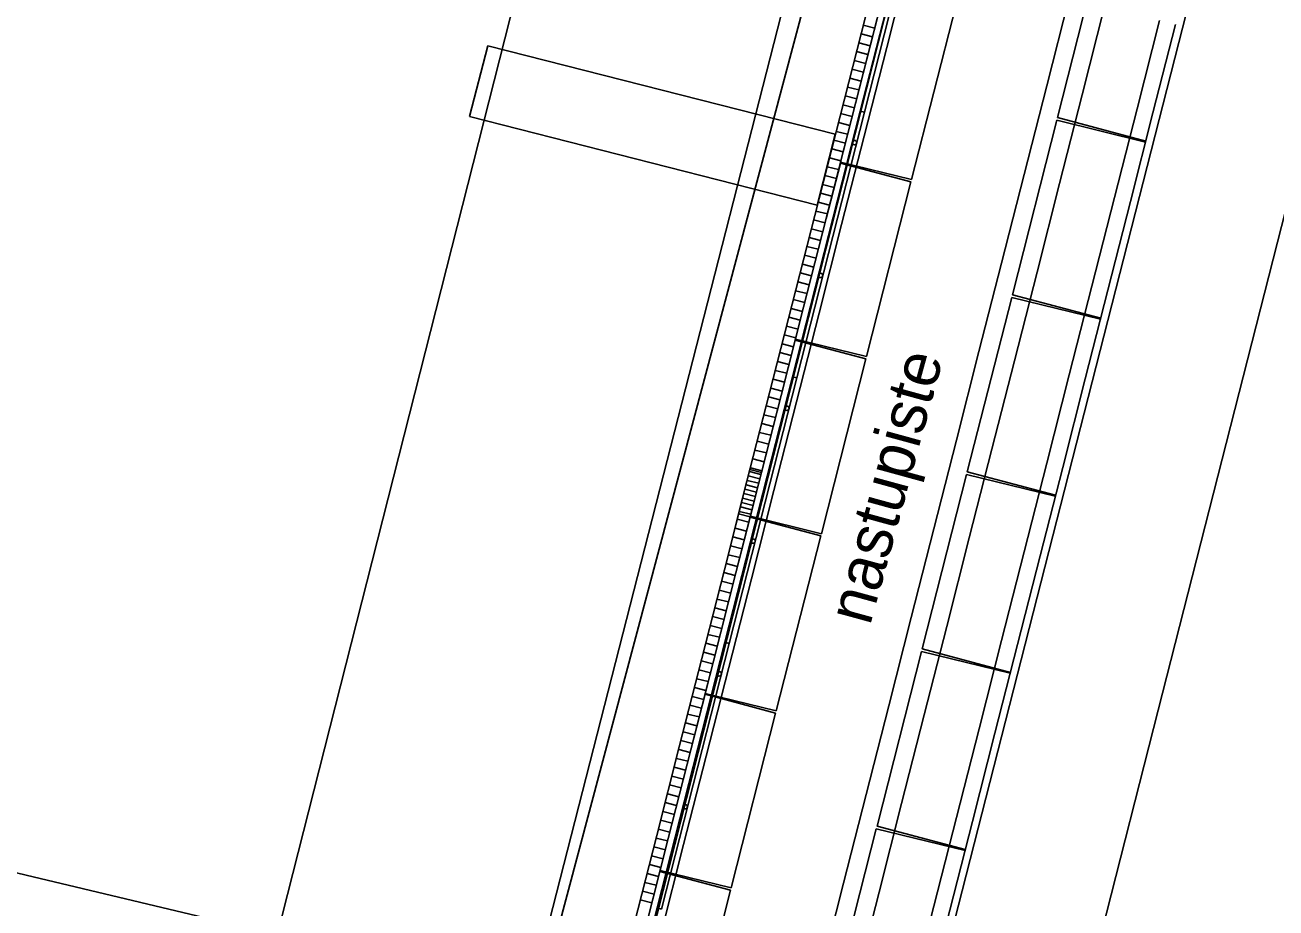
# Model space of a CAD drawing. Extents: x -733601 to -733291, y -1137892 to -1137187.
# Drawn here: x -733465.26 to -733451.57, y -1137672.4 to -1137662.74 of the extents above; entities that cross this region are included whole.
import ezdxf

# ---------------------------------------------------------------- set-up
doc = ezdxf.new("R2010")
doc.units = 0
for name, color, linetype in [('Rozvrzeni', 7, 'Continuous'), ('SIT_PUV_BUS', 7, 'Continuous'), ('SIT_PUV_ZELEZNICE', 7, 'Continuous')]:
    doc.layers.add(name, color=color, linetype=linetype)

msp = doc.modelspace()

# ---------------------------------------------------------------- linework, layer by layer
at = {"layer": 'Rozvrzeni'}
msp.add_lwpolyline([(-733564.934, -1137648.317), (-733492.008, -1137341.875), (-733347.542, -1137376.254), (-733420.468, -1137682.696)], close=True, dxfattribs=at)
at = {"layer": 'SIT_PUV_BUS'}
for p, q in [((-733456.56, -1137649.32), (-733464.08, -1137678.93)), ((-733453.45, -1137650.19), (-733460.1, -1137675.18)), ((-733455.27, -1137660.37), (-733460.18, -1137679.73)), ((-733452.43, -1137662.15), (-733466.53, -1137717.32))]:
    msp.add_line(p, q, dxfattribs=at)
at = {"layer": 'SIT_PUV_ZELEZNICE'}
for p, q in [((-733453.472, -1137661.842), (-733453.958, -1137663.751)), ((-733456.116, -1137663.679), (-733455.768, -1137662.313)), ((-733456.07, -1137663.691), (-733455.721, -1137662.325)), ((-733455.067, -1137662.515), (-733455.555, -1137664.428)), ((-733455.958, -1137662.77), (-733456.084, -1137662.738)), ((-733455.983, -1137662.867), (-733456.108, -1137662.835)), ((-733460.193, -1137662.964), (-733460.392, -1137663.739)), ((-733456.39, -1137663.933), (-733460.193, -1137662.964)), ((-733456.007, -1137662.964), (-733456.133, -1137662.931)), ((-733456.057, -1137663.157), (-733456.183, -1137663.125)), ((-733456.032, -1137663.06), (-733456.158, -1137663.028)), ((-733456.081, -1137663.254), (-733456.207, -1137663.222)), ((-733456.131, -1137663.448), (-733456.257, -1137663.416)), ((-733456.106, -1137663.351), (-733456.232, -1137663.319)), ((-733456.155, -1137663.545), (-733456.281, -1137663.513)), ((-733456.857, -1137666.586), (-733456.116, -1137663.679)), ((-733456.81, -1137666.598), (-733456.07, -1137663.691)), ((-733456.18, -1137663.642), (-733456.306, -1137663.61)), ((-733456.07, -1137663.691), (-733456.116, -1137663.679)), ((-733456.116, -1137663.679), (-733456.07, -1137663.691)), ((-733460.392, -1137663.739), (-733456.587, -1137664.709)), ((-733456.229, -1137663.836), (-733456.355, -1137663.804)), ((-733456.205, -1137663.739), (-733456.331, -1137663.707)), ((-733453.966, -1137663.78), (-733454.452, -1137665.689)), ((-733452.994, -1137664.018), (-733453.966, -1137663.78)), ((-733453.958, -1137663.751), (-733452.992, -1137664.008)), ((-733456.587, -1137664.709), (-733456.39, -1137663.933)), ((-733456.254, -1137663.933), (-733456.38, -1137663.901)), ((-733456.303, -1137664.126), (-733456.429, -1137664.094)), ((-733456.279, -1137664.03), (-733456.405, -1137663.997)), ((-733456.328, -1137664.223), (-733456.454, -1137664.191)), ((-733456.334, -1137664.248), (-733455.561, -1137664.453)), ((-733455.555, -1137664.428), (-733456.332, -1137664.238)), ((-733456.377, -1137664.417), (-733456.503, -1137664.385)), ((-733456.353, -1137664.32), (-733456.479, -1137664.288)), ((-733456.402, -1137664.514), (-733456.528, -1137664.482)), ((-733455.561, -1137664.453), (-733456.048, -1137666.366)), ((-733456.427, -1137664.611), (-733456.553, -1137664.579)), ((-733456.476, -1137664.805), (-733456.602, -1137664.773)), ((-733456.452, -1137664.708), (-733456.578, -1137664.676)), ((-733456.501, -1137664.902), (-733456.627, -1137664.87)), ((-733456.55, -1137665.095), (-733456.676, -1137665.063)), ((-733456.526, -1137664.999), (-733456.652, -1137664.967)), ((-733456.575, -1137665.192), (-733456.701, -1137665.16)), ((-733456.6, -1137665.289), (-733456.726, -1137665.257)), ((-733456.649, -1137665.483), (-733456.775, -1137665.451)), ((-733456.624, -1137665.386), (-733456.75, -1137665.354)), ((-733456.674, -1137665.58), (-733456.8, -1137665.548)), ((-733456.723, -1137665.774), (-733456.849, -1137665.742)), ((-733456.698, -1137665.677), (-733456.824, -1137665.645)), ((-733454.459, -1137665.719), (-733454.946, -1137667.628)), ((-733453.488, -1137665.956), (-733454.459, -1137665.719)), ((-733454.452, -1137665.689), (-733453.485, -1137665.946)), ((-733456.748, -1137665.871), (-733456.874, -1137665.839)), ((-733456.772, -1137665.968), (-733456.898, -1137665.936)), ((-733456.822, -1137666.161), (-733456.948, -1137666.129)), ((-733456.797, -1137666.065), (-733456.923, -1137666.032)), ((-733456.847, -1137666.258), (-733456.972, -1137666.226)), ((-733456.828, -1137666.186), (-733456.055, -1137666.391)), ((-733456.048, -1137666.366), (-733456.826, -1137666.176)), ((-733456.896, -1137666.452), (-733457.022, -1137666.42)), ((-733456.871, -1137666.355), (-733456.997, -1137666.323)), ((-733456.055, -1137666.391), (-733456.542, -1137668.304)), ((-733456.921, -1137666.549), (-733457.047, -1137666.517)), ((-733457.597, -1137669.493), (-733456.857, -1137666.586)), ((-733457.551, -1137669.505), (-733456.81, -1137666.598)), ((-733456.97, -1137666.743), (-733457.096, -1137666.711)), ((-733456.945, -1137666.646), (-733457.071, -1137666.614)), ((-733456.857, -1137666.586), (-733456.81, -1137666.598)), ((-733456.81, -1137666.598), (-733456.857, -1137666.586)), ((-733456.995, -1137666.84), (-733457.121, -1137666.808)), ((-733457.019, -1137666.937), (-733457.145, -1137666.905)), ((-733457.069, -1137667.131), (-733457.195, -1137667.098)), ((-733457.044, -1137667.034), (-733457.17, -1137667.002)), ((-733457.093, -1137667.227), (-733457.219, -1137667.195)), ((-733457.143, -1137667.421), (-733457.269, -1137667.389)), ((-733457.118, -1137667.324), (-733457.244, -1137667.292)), ((-733457.167, -1137667.518), (-733457.293, -1137667.486)), ((-733457.203, -1137667.656), (-733457.329, -1137667.624)), ((-733457.323, -1137667.603), (-733457.197, -1137667.635)), ((-733457.192, -1137667.615), (-733457.318, -1137667.583)), ((-733454.953, -1137667.657), (-733455.439, -1137669.566)), ((-733453.982, -1137667.894), (-733454.953, -1137667.657)), ((-733454.946, -1137667.628), (-733453.979, -1137667.884)), ((-733457.24, -1137667.801), (-733457.366, -1137667.769)), ((-733457.227, -1137667.753), (-733457.353, -1137667.721)), ((-733457.215, -1137667.705), (-733457.341, -1137667.672)), ((-733457.277, -1137667.947), (-733457.403, -1137667.915)), ((-733457.264, -1137667.898), (-733457.39, -1137667.866)), ((-733457.252, -1137667.85), (-733457.378, -1137667.818)), ((-733457.314, -1137668.092), (-733457.44, -1137668.06)), ((-733457.301, -1137668.044), (-733457.427, -1137668.012)), ((-733457.289, -1137667.995), (-733457.415, -1137667.963)), ((-733457.336, -1137668.179), (-733457.462, -1137668.146)), ((-733457.447, -1137668.087), (-733457.321, -1137668.119)), ((-733457.322, -1137668.124), (-733456.548, -1137668.329)), ((-733456.542, -1137668.304), (-733457.319, -1137668.114)), ((-733457.385, -1137668.372), (-733457.511, -1137668.34)), ((-733457.36, -1137668.275), (-733457.486, -1137668.243)), ((-733456.548, -1137668.329), (-733457.036, -1137670.242)), ((-733457.41, -1137668.469), (-733457.536, -1137668.437)), ((-733457.434, -1137668.566), (-733457.56, -1137668.534)), ((-733457.484, -1137668.76), (-733457.61, -1137668.728)), ((-733457.459, -1137668.663), (-733457.585, -1137668.631)), ((-733457.508, -1137668.857), (-733457.634, -1137668.825)), ((-733457.558, -1137669.051), (-733457.684, -1137669.019)), ((-733457.533, -1137668.954), (-733457.659, -1137668.922)), ((-733457.583, -1137669.148), (-733457.708, -1137669.115)), ((-733457.632, -1137669.341), (-733457.758, -1137669.309)), ((-733457.607, -1137669.244), (-733457.733, -1137669.212)), ((-733457.657, -1137669.438), (-733457.783, -1137669.406)), ((-733458.338, -1137672.4), (-733457.597, -1137669.493)), ((-733458.291, -1137672.412), (-733457.551, -1137669.505)), ((-733457.681, -1137669.535), (-733457.807, -1137669.503)), ((-733457.597, -1137669.493), (-733457.551, -1137669.505)), ((-733457.551, -1137669.505), (-733457.597, -1137669.493)), ((-733455.439, -1137669.566), (-733454.473, -1137669.822)), ((-733457.731, -1137669.729), (-733457.857, -1137669.697)), ((-733457.706, -1137669.632), (-733457.832, -1137669.6)), ((-733455.447, -1137669.595), (-733455.933, -1137671.504)), ((-733454.475, -1137669.832), (-733455.447, -1137669.595)), ((-733457.755, -1137669.826), (-733457.881, -1137669.794)), ((-733457.805, -1137670.02), (-733457.931, -1137669.988)), ((-733457.78, -1137669.923), (-733457.906, -1137669.891)), ((-733457.829, -1137670.117), (-733457.955, -1137670.085)), ((-733457.815, -1137670.062), (-733457.042, -1137670.267)), ((-733457.036, -1137670.242), (-733457.813, -1137670.052)), ((-733457.854, -1137670.214), (-733457.98, -1137670.181)), ((-733457.042, -1137670.267), (-733457.529, -1137672.18)), ((-733457.903, -1137670.407), (-733458.029, -1137670.375)), ((-733457.879, -1137670.31), (-733458.005, -1137670.278)), ((-733457.928, -1137670.504), (-733458.054, -1137670.472)), ((-733457.977, -1137670.698), (-733458.103, -1137670.666)), ((-733457.953, -1137670.601), (-733458.079, -1137670.569)), ((-733458.002, -1137670.795), (-733458.128, -1137670.763)), ((-733458.027, -1137670.892), (-733458.153, -1137670.86)), ((-733458.076, -1137671.086), (-733458.202, -1137671.054)), ((-733458.052, -1137670.989), (-733458.178, -1137670.957)), ((-733458.101, -1137671.183), (-733458.227, -1137671.15)), ((-733458.15, -1137671.376), (-733458.276, -1137671.344)), ((-733458.126, -1137671.279), (-733458.252, -1137671.247)), ((-733458.175, -1137671.473), (-733458.301, -1137671.441)), ((-733458.224, -1137671.667), (-733458.35, -1137671.635)), ((-733458.2, -1137671.57), (-733458.326, -1137671.538)), ((-733455.941, -1137671.533), (-733456.427, -1137673.442)), ((-733454.969, -1137671.77), (-733455.941, -1137671.533)), ((-733455.933, -1137671.504), (-733454.967, -1137671.76)), ((-733458.249, -1137671.764), (-733458.375, -1137671.732)), ((-733458.274, -1137671.861), (-733458.4, -1137671.829)), ((-733458.323, -1137672.055), (-733458.449, -1137672.023)), ((-733458.298, -1137671.958), (-733458.424, -1137671.926)), ((-733458.309, -1137672), (-733457.536, -1137672.205)), ((-733457.529, -1137672.18), (-733458.307, -1137671.99)), ((-733458.348, -1137672.152), (-733458.474, -1137672.12)), ((-733458.397, -1137672.345), (-733458.523, -1137672.313)), ((-733458.372, -1137672.249), (-733458.498, -1137672.216)), ((-733457.536, -1137672.205), (-733458.023, -1137674.118)), ((-733459.079, -1137675.308), (-733458.338, -1137672.4)), ((-733458.338, -1137672.4), (-733458.291, -1137672.412)), ((-733458.291, -1137672.412), (-733458.338, -1137672.4))]:
    msp.add_line(p, q, dxfattribs=at)
for points in [[(-733473.591, -1137751.638), (-733472.603, -1137747.76), (-733470.135, -1137738.069), (-733467.666, -1137728.379), (-733465.198, -1137718.688), (-733462.729, -1137708.998), (-733460.26, -1137699.307), (-733457.792, -1137689.617), (-733455.323, -1137679.926), (-733452.855, -1137670.236), (-733450.386, -1137660.545), (-733448.734, -1137654.061), (-733447.917, -1137650.855), (-733445.432, -1137641.168), (-733442.928, -1137631.487), (-733440.405, -1137621.811), (-733437.862, -1137612.139), (-733437.8, -1137611.906), (-733435.314, -1137602.469), (-733432.775, -1137592.797), (-733432.613, -1137592.177)], [(-733462.935, -1137685.963), (-733461.332, -1137679.64), (-733453.759, -1137650.014), (-733456.593, -1137649.288), (-733465.899, -1137646.951)], [(-733461.011, -1137683.337), (-733460.764, -1137682.368), (-733460.518, -1137681.399), (-733460.271, -1137680.429), (-733460.179, -1137680.069), (-733460.024, -1137679.46), (-733459.777, -1137678.491), (-733459.53, -1137677.522), (-733459.283, -1137676.553), (-733459.036, -1137675.584), (-733458.789, -1137674.615), (-733458.543, -1137673.646), (-733458.296, -1137672.676), (-733458.049, -1137671.707), (-733457.802, -1137670.738), (-733457.555, -1137669.769), (-733457.308, -1137668.8), (-733457.061, -1137667.83), (-733456.814, -1137666.861), (-733456.567, -1137665.892), (-733456.32, -1137664.922), (-733456.073, -1137663.953), (-733455.827, -1137662.983), (-733455.58, -1137662.014)], [(-733461.306, -1137683.236), (-733461.059, -1137682.267), (-733460.812, -1137681.298), (-733460.565, -1137680.329), (-733460.473, -1137679.969), (-733460.318, -1137679.36), (-733460.071, -1137678.391), (-733459.825, -1137677.422), (-733459.578, -1137676.453), (-733459.331, -1137675.484), (-733459.084, -1137674.515), (-733458.837, -1137673.546), (-733458.59, -1137672.576), (-733458.343, -1137671.607), (-733458.096, -1137670.638), (-733457.849, -1137669.669), (-733457.602, -1137668.699), (-733457.356, -1137667.73), (-733457.109, -1137666.761), (-733456.862, -1137665.791), (-733456.615, -1137664.822), (-733455.965, -1137662.273)], [(-733461.18, -1137683.269), (-733460.933, -1137682.299), (-733460.686, -1137681.33), (-733460.439, -1137680.361), (-733460.347, -1137680.001), (-733460.192, -1137679.392), (-733459.945, -1137678.423), (-733459.699, -1137677.454), (-733459.452, -1137676.485), (-733459.205, -1137675.516), (-733458.958, -1137674.547), (-733458.711, -1137673.578), (-733458.464, -1137672.608), (-733458.217, -1137671.639), (-733457.97, -1137670.67), (-733457.723, -1137669.701), (-733457.477, -1137668.731), (-733457.23, -1137667.762), (-733456.983, -1137666.793), (-733456.736, -1137665.824), (-733456.489, -1137664.854), (-733455.839, -1137662.305)], [(-733459.014, -1137682.788), (-733458.767, -1137681.819), (-733458.52, -1137680.85), (-733458.429, -1137680.49), (-733458.274, -1137679.881), (-733458.027, -1137678.912), (-733457.78, -1137677.943), (-733457.533, -1137676.974), (-733457.286, -1137676.005), (-733457.039, -1137675.036), (-733456.792, -1137674.066), (-733456.545, -1137673.097), (-733456.299, -1137672.128), (-733456.052, -1137671.159), (-733455.805, -1137670.189), (-733455.558, -1137669.22), (-733455.311, -1137668.251), (-733455.064, -1137667.282), (-733454.817, -1137666.312), (-733454.57, -1137665.343), (-733454.323, -1137664.374), (-733454.076, -1137663.404), (-733453.829, -1137662.435)], [(-733458.626, -1137682.887), (-733458.38, -1137681.918), (-733458.133, -1137680.949), (-733458.041, -1137680.589), (-733457.886, -1137679.98), (-733457.639, -1137679.011), (-733457.392, -1137678.042), (-733457.145, -1137677.073), (-733456.898, -1137676.103), (-733456.652, -1137675.134), (-733456.405, -1137674.165), (-733456.158, -1137673.196), (-733455.911, -1137672.227), (-733455.664, -1137671.257), (-733455.417, -1137670.288), (-733455.17, -1137669.319), (-733454.923, -1137668.35), (-733454.676, -1137667.38), (-733454.429, -1137666.411), (-733454.182, -1137665.442), (-733453.936, -1137664.472), (-733453.689, -1137663.503), (-733453.442, -1137662.534)], [(-733458.026, -1137683.04), (-733457.779, -1137682.071), (-733457.532, -1137681.102), (-733457.44, -1137680.742), (-733457.285, -1137680.133), (-733457.038, -1137679.164), (-733456.791, -1137678.195), (-733456.545, -1137677.226), (-733456.298, -1137676.256), (-733456.051, -1137675.287), (-733455.804, -1137674.318), (-733455.557, -1137673.349), (-733455.31, -1137672.38), (-733455.063, -1137671.411), (-733454.816, -1137670.441), (-733454.569, -1137669.472), (-733454.322, -1137668.503), (-733454.076, -1137667.533), (-733453.829, -1137666.564), (-733453.582, -1137665.595), (-733453.335, -1137664.625), (-733453.088, -1137663.656), (-733452.841, -1137662.687)], [(-733457.851, -1137683.084), (-733457.604, -1137682.115), (-733457.358, -1137681.146), (-733457.266, -1137680.786), (-733457.111, -1137680.177), (-733456.864, -1137679.208), (-733456.617, -1137678.239), (-733456.37, -1137677.27), (-733456.123, -1137676.301), (-733455.876, -1137675.332), (-733455.629, -1137674.363), (-733455.383, -1137673.393), (-733455.136, -1137672.424), (-733454.889, -1137671.455), (-733454.642, -1137670.486), (-733454.395, -1137669.516), (-733454.148, -1137668.547), (-733453.901, -1137667.578), (-733453.654, -1137666.609), (-733453.407, -1137665.639), (-733453.16, -1137664.67), (-733452.913, -1137663.7), (-733452.666, -1137662.731)], [(-733458.464, -1137672.608), (-733458.309, -1137672), (-733458.307, -1137671.99), (-733458.217, -1137671.639), (-733457.97, -1137670.67), (-733457.815, -1137670.062), (-733457.813, -1137670.052), (-733457.723, -1137669.701), (-733457.477, -1137668.731), (-733457.322, -1137668.124), (-733457.321, -1137668.119), (-733457.447, -1137668.087), (-733457.602, -1137668.699), (-733457.849, -1137669.669), (-733458.096, -1137670.638), (-733458.343, -1137671.607), (-733458.59, -1137672.576)]]:
    msp.add_lwpolyline(points, dxfattribs=at)
for points in [[(-733455.839, -1137662.305), (-733455.965, -1137662.273), (-733456.615, -1137664.822), (-733456.862, -1137665.791), (-733457.109, -1137666.761), (-733457.323, -1137667.603), (-733457.197, -1137667.635), (-733456.983, -1137666.793), (-733456.828, -1137666.186), (-733456.826, -1137666.176), (-733456.736, -1137665.824), (-733456.489, -1137664.854), (-733456.334, -1137664.248), (-733456.332, -1137664.238), (-733455.841, -1137662.31)], [(-733457.23, -1137667.762), (-733457.197, -1137667.635), (-733457.323, -1137667.603), (-733457.356, -1137667.73), (-733457.447, -1137668.087), (-733457.321, -1137668.119), (-733457.319, -1137668.114)]]:
    msp.add_lwpolyline(points, close=True, dxfattribs=at)
for centre in [(-733456.179, -1137664.024), (-733456.55, -1137665.478), (-733456.92, -1137666.931), (-733457.29, -1137668.385), (-733457.66, -1137669.838), (-733458.031, -1137671.292)]:
    msp.add_circle(centre, 0.0241, dxfattribs=at)

# ---------------------------------------------------------------- texts
at = {"layer": 'SIT_PUV_BUS'}
msp.add_text('nastupiste', height=0.5, rotation=74.7, dxfattribs=at).set_placement((-733456.01, -1137669.32))

doc.saveas('drawing.dxf')
